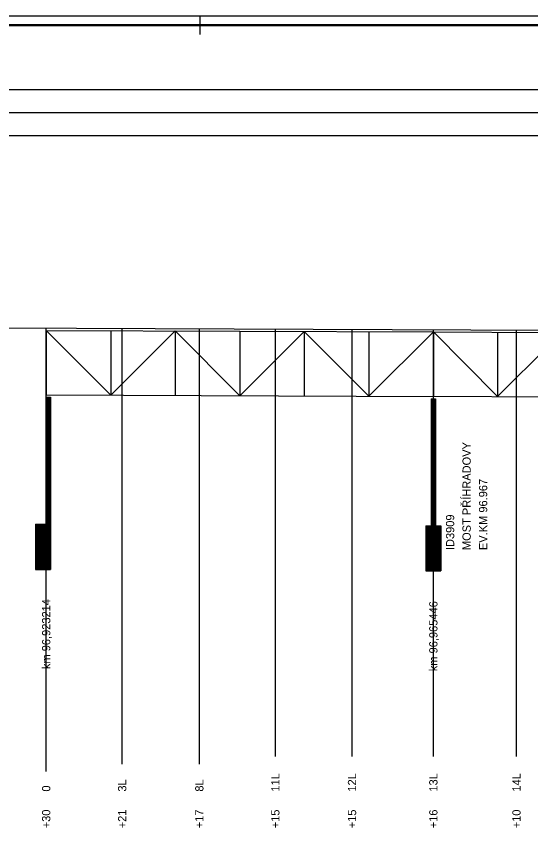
# Model space of a CAD drawing. Extents: x 0 to 10087, y -805 to 297.
# Drawn here: x 1219.9 to 1332.1, y 120.1 to 297 of the extents above; entities that cross this region are included whole.
import ezdxf

# ---------------------------------------------------------------- set-up
doc = ezdxf.new("R2010")
doc.units = 0
for name, color, linetype in [('CARKY_HODNOT', 7, 'Continuous'), ('NIVELETA_CARA', 7, 'Continuous'), ('OBJEKTY_TEXT', 7, 'Continuous'), ('OBJEKTY_TVAR', 7, 'Continuous'), ('RAM', 7, 'Continuous'), ('TEXT', 7, 'Continuous')]:
    doc.layers.add(name, color=color, linetype=linetype)

msp = doc.modelspace()

# ---------------------------------------------------------------- linework, layer by layer
at = {"layer": 'CARKY_HODNOT'}
for p, q in [((1226.43, 138.35), (1226.43, 229.03)), ((1243.01, 138.35), (1243.01, 228.96)), ((1259.84, 138.35), (1259.84, 228.89)), ((1276.42, 138.35), (1276.42, 228.82)), ((1293.15, 138.35), (1293.15, 228.75)), ((1310.89, 138.35), (1310.89, 228.68)), ((1329.03, 138.35), (1329.03, 228.6)), ((1226.43, 132.35), (1226.43, 138.35)), ((1243.01, 134), (1243.01, 138.35)), ((1259.84, 134), (1259.84, 138.35)), ((1276.42, 135.65), (1276.42, 138.35)), ((1293.15, 135.65), (1293.15, 138.35)), ((1310.89, 135.65), (1310.89, 138.35)), ((1329.03, 135.65), (1329.03, 138.35))]:
    msp.add_line(p, q, dxfattribs=at)
at = {"layer": 'NIVELETA_CARA'}
for p, q in [((300, 281), (8321.33, 281)), ((300, 276), (8321.33, 276)), ((300, 271), (8321.33, 271)), ((1153.84, 229.33), (1363.14, 228.46))]:
    msp.add_line(p, q, dxfattribs=at)
at = {"layer": 'OBJEKTY_TVAR'}
for p, q in [((1226.43, 228.53), (1240.5, 214.39)), ((1226.43, 228.53), (1226.43, 214.45)), ((1226.43, 228.53), (1310.89, 228.18)), ((1240.5, 228.47), (1240.5, 214.39)), ((1240.5, 214.39), (1254.58, 228.41)), ((1254.58, 228.41), (1254.58, 214.33)), ((1254.58, 228.41), (1268.66, 214.28)), ((1268.66, 228.35), (1268.66, 214.28)), ((1268.66, 214.28), (1282.74, 228.29)), ((1282.74, 228.29), (1282.74, 214.22)), ((1282.74, 228.29), (1296.81, 214.16)), ((1296.81, 228.24), (1296.81, 214.16)), ((1296.81, 214.16), (1310.89, 228.18)), ((1310.89, 228.18), (1310.89, 214.1)), ((1310.89, 228.18), (1324.9, 214.11)), ((1310.89, 228.18), (1310.89, 214.17)), ((1310.89, 228.18), (1394.92, 227.81)), ((1324.9, 228.12), (1324.9, 214.11)), ((1324.9, 214.11), (1338.9, 228.06)), ((1226.43, 214.45), (1310.89, 214.1)), ((1310.89, 214.17), (1394.92, 213.81)), ((1226.43, 213.95), (1226.43, 186.3)), ((1226.43, 213.95), (1227.37, 213.95)), ((1226.53, 213.95), (1226.53, 186.3)), ((1226.63, 213.95), (1226.63, 186.3)), ((1226.73, 213.95), (1226.73, 186.3)), ((1226.83, 213.95), (1226.83, 186.3)), ((1226.9, 213.95), (1226.9, 186.3)), ((1226.93, 213.95), (1226.93, 186.3)), ((1227.03, 213.95), (1227.03, 186.3)), ((1227.13, 213.95), (1227.13, 186.3)), ((1227.23, 213.95), (1227.23, 186.3)), ((1227.33, 213.95), (1227.33, 186.3)), ((1227.37, 213.95), (1227.37, 186.3)), ((1310.42, 213.6), (1310.42, 185.95)), ((1310.42, 213.6), (1311.36, 213.6)), ((1310.52, 213.6), (1310.52, 185.95)), ((1310.62, 213.6), (1310.62, 185.95)), ((1310.72, 213.6), (1310.72, 185.95)), ((1310.82, 213.6), (1310.82, 185.95)), ((1310.89, 213.6), (1310.89, 185.95)), ((1310.92, 213.6), (1310.92, 185.95)), ((1311.02, 213.6), (1311.02, 185.95)), ((1311.12, 213.6), (1311.12, 185.95)), ((1311.22, 213.6), (1311.22, 185.95)), ((1311.32, 213.6), (1311.32, 185.95)), ((1311.36, 213.6), (1311.36, 185.95)), ((1224.08, 186.3), (1227.37, 186.3)), ((1224.08, 186.3), (1224.08, 176.44)), ((1224.08, 186.2), (1227.37, 186.2)), ((1224.08, 186.1), (1227.37, 186.1)), ((1224.08, 186), (1227.37, 186)), ((1224.08, 185.9), (1227.37, 185.9)), ((1224.08, 185.8), (1227.37, 185.8)), ((1227.37, 186.3), (1227.37, 176.44)), ((1309.25, 185.95), (1312.53, 185.95)), ((1309.25, 185.95), (1309.25, 176.09)), ((1309.25, 185.85), (1312.53, 185.85)), ((1309.25, 185.75), (1312.53, 185.75)), ((1312.53, 185.95), (1312.53, 176.09)), ((1224.08, 185.7), (1227.37, 185.7)), ((1224.08, 185.6), (1227.37, 185.6)), ((1224.08, 185.5), (1227.37, 185.5)), ((1224.08, 185.4), (1227.37, 185.4)), ((1224.08, 185.3), (1227.37, 185.3)), ((1224.08, 185.2), (1227.37, 185.2)), ((1224.08, 185.1), (1227.37, 185.1)), ((1224.08, 185), (1227.37, 185)), ((1224.08, 184.9), (1227.37, 184.9)), ((1224.08, 184.8), (1227.37, 184.8)), ((1224.08, 184.7), (1227.37, 184.7)), ((1224.08, 184.6), (1227.37, 184.6)), ((1224.08, 184.5), (1227.37, 184.5)), ((1224.08, 184.4), (1227.37, 184.4)), ((1224.08, 184.3), (1227.37, 184.3)), ((1224.08, 184.2), (1227.37, 184.2)), ((1224.08, 184.1), (1227.37, 184.1)), ((1224.08, 184), (1227.37, 184)), ((1309.25, 185.65), (1312.53, 185.65)), ((1309.25, 185.55), (1312.53, 185.55)), ((1309.25, 185.45), (1312.53, 185.45)), ((1309.25, 185.35), (1312.53, 185.35)), ((1309.25, 185.25), (1312.53, 185.25)), ((1309.25, 185.15), (1312.53, 185.15)), ((1309.25, 185.05), (1312.53, 185.05)), ((1309.25, 184.95), (1312.53, 184.95)), ((1309.25, 184.85), (1312.53, 184.85)), ((1309.25, 184.75), (1312.53, 184.75)), ((1309.25, 184.65), (1312.53, 184.65)), ((1309.25, 184.55), (1312.53, 184.55)), ((1309.25, 184.45), (1312.53, 184.45)), ((1309.25, 184.35), (1312.53, 184.35)), ((1309.25, 184.25), (1312.53, 184.25)), ((1309.25, 184.15), (1312.53, 184.15)), ((1309.25, 184.05), (1312.53, 184.05)), ((1224.08, 183.9), (1227.37, 183.9)), ((1224.08, 183.8), (1227.37, 183.8)), ((1224.08, 183.7), (1227.37, 183.7)), ((1224.08, 183.6), (1227.37, 183.6)), ((1224.08, 183.5), (1227.37, 183.5)), ((1224.08, 183.4), (1227.37, 183.4)), ((1224.08, 183.3), (1227.37, 183.3)), ((1224.08, 183.2), (1227.37, 183.2)), ((1224.08, 183.1), (1227.37, 183.1)), ((1224.08, 183), (1227.37, 183)), ((1224.08, 182.9), (1227.37, 182.9)), ((1224.08, 182.8), (1227.37, 182.8)), ((1224.08, 182.7), (1227.37, 182.7)), ((1224.08, 182.6), (1227.37, 182.6)), ((1224.08, 182.5), (1227.37, 182.5)), ((1224.08, 182.4), (1227.37, 182.4)), ((1224.08, 182.3), (1227.37, 182.3)), ((1224.08, 182.2), (1227.37, 182.2)), ((1309.25, 183.95), (1312.53, 183.95)), ((1309.25, 183.85), (1312.53, 183.85)), ((1309.25, 183.75), (1312.53, 183.75)), ((1309.25, 183.65), (1312.53, 183.65)), ((1309.25, 183.55), (1312.53, 183.55)), ((1309.25, 183.45), (1312.53, 183.45)), ((1309.25, 183.35), (1312.53, 183.35)), ((1309.25, 183.25), (1312.53, 183.25)), ((1309.25, 183.15), (1312.53, 183.15)), ((1309.25, 183.05), (1312.53, 183.05)), ((1309.25, 182.95), (1312.53, 182.95)), ((1309.25, 182.85), (1312.53, 182.85)), ((1309.25, 182.75), (1312.53, 182.75)), ((1309.25, 182.65), (1312.53, 182.65)), ((1309.25, 182.55), (1312.53, 182.55)), ((1309.25, 182.45), (1312.53, 182.45)), ((1309.25, 182.35), (1312.53, 182.35)), ((1309.25, 182.25), (1312.53, 182.25)), ((1224.08, 182.1), (1227.37, 182.1)), ((1224.08, 182), (1227.37, 182)), ((1224.08, 181.9), (1227.37, 181.9)), ((1224.08, 181.8), (1227.37, 181.8)), ((1224.08, 181.7), (1227.37, 181.7)), ((1224.08, 181.6), (1227.37, 181.6)), ((1224.08, 181.5), (1227.37, 181.5)), ((1224.08, 181.4), (1227.37, 181.4)), ((1224.08, 181.3), (1227.37, 181.3)), ((1224.08, 181.2), (1227.37, 181.2)), ((1224.08, 181.1), (1227.37, 181.1)), ((1224.08, 181), (1227.37, 181)), ((1224.08, 180.9), (1227.37, 180.9)), ((1224.08, 180.8), (1227.37, 180.8)), ((1224.08, 180.7), (1227.37, 180.7)), ((1224.08, 180.6), (1227.37, 180.6)), ((1224.08, 180.5), (1227.37, 180.5)), ((1309.25, 182.15), (1312.53, 182.15)), ((1309.25, 182.05), (1312.53, 182.05)), ((1309.25, 181.95), (1312.53, 181.95)), ((1309.25, 181.85), (1312.53, 181.85)), ((1309.25, 181.75), (1312.53, 181.75)), ((1309.25, 181.65), (1312.53, 181.65)), ((1309.25, 181.55), (1312.53, 181.55)), ((1309.25, 181.45), (1312.53, 181.45)), ((1309.25, 181.35), (1312.53, 181.35)), ((1309.25, 181.25), (1312.53, 181.25)), ((1309.25, 181.15), (1312.53, 181.15)), ((1309.25, 181.05), (1312.53, 181.05)), ((1309.25, 180.95), (1312.53, 180.95)), ((1309.25, 180.85), (1312.53, 180.85)), ((1309.25, 180.75), (1312.53, 180.75)), ((1309.25, 180.65), (1312.53, 180.65)), ((1309.25, 180.55), (1312.53, 180.55)), ((1309.25, 180.45), (1312.53, 180.45)), ((1224.08, 180.4), (1227.37, 180.4)), ((1224.08, 180.3), (1227.37, 180.3)), ((1224.08, 180.2), (1227.37, 180.2)), ((1224.08, 180.1), (1227.37, 180.1)), ((1224.08, 180), (1227.37, 180)), ((1224.08, 179.9), (1227.37, 179.9)), ((1224.08, 179.8), (1227.37, 179.8)), ((1224.08, 179.7), (1227.37, 179.7)), ((1224.08, 179.6), (1227.37, 179.6)), ((1224.08, 179.5), (1227.37, 179.5)), ((1224.08, 179.4), (1227.37, 179.4)), ((1224.08, 179.3), (1227.37, 179.3)), ((1224.08, 179.2), (1227.37, 179.2)), ((1224.08, 179.1), (1227.37, 179.1)), ((1224.08, 179), (1227.37, 179)), ((1224.08, 178.9), (1227.37, 178.9)), ((1224.08, 178.8), (1227.37, 178.8)), ((1224.08, 178.7), (1227.37, 178.7)), ((1309.25, 180.35), (1312.53, 180.35)), ((1309.25, 180.25), (1312.53, 180.25)), ((1309.25, 180.15), (1312.53, 180.15)), ((1309.25, 180.05), (1312.53, 180.05)), ((1309.25, 179.95), (1312.53, 179.95)), ((1309.25, 179.85), (1312.53, 179.85)), ((1309.25, 179.75), (1312.53, 179.75)), ((1309.25, 179.65), (1312.53, 179.65)), ((1309.25, 179.55), (1312.53, 179.55)), ((1309.25, 179.45), (1312.53, 179.45)), ((1309.25, 179.35), (1312.53, 179.35)), ((1309.25, 179.25), (1312.53, 179.25)), ((1309.25, 179.15), (1312.53, 179.15)), ((1309.25, 179.05), (1312.53, 179.05)), ((1309.25, 178.95), (1312.53, 178.95)), ((1309.25, 178.85), (1312.53, 178.85)), ((1309.25, 178.75), (1312.53, 178.75)), ((1224.08, 178.6), (1227.37, 178.6)), ((1224.08, 178.5), (1227.37, 178.5)), ((1224.08, 178.4), (1227.37, 178.4)), ((1224.08, 178.3), (1227.37, 178.3)), ((1224.08, 178.2), (1227.37, 178.2)), ((1224.08, 178.1), (1227.37, 178.1)), ((1224.08, 178), (1227.37, 178)), ((1224.08, 177.9), (1227.37, 177.9)), ((1224.08, 177.8), (1227.37, 177.8)), ((1224.08, 177.7), (1227.37, 177.7)), ((1224.08, 177.6), (1227.37, 177.6)), ((1224.08, 177.5), (1227.37, 177.5)), ((1224.08, 177.4), (1227.37, 177.4)), ((1224.08, 177.3), (1227.37, 177.3)), ((1224.08, 177.2), (1227.37, 177.2)), ((1224.08, 177.1), (1227.37, 177.1)), ((1224.08, 177), (1227.37, 177)), ((1224.08, 176.9), (1227.37, 176.9)), ((1309.25, 178.65), (1312.53, 178.65)), ((1309.25, 178.55), (1312.53, 178.55)), ((1309.25, 178.45), (1312.53, 178.45)), ((1309.25, 178.35), (1312.53, 178.35)), ((1309.25, 178.25), (1312.53, 178.25)), ((1309.25, 178.15), (1312.53, 178.15)), ((1309.25, 178.05), (1312.53, 178.05)), ((1309.25, 177.95), (1312.53, 177.95)), ((1309.25, 177.85), (1312.53, 177.85)), ((1309.25, 177.75), (1312.53, 177.75)), ((1309.25, 177.65), (1312.53, 177.65)), ((1309.25, 177.55), (1312.53, 177.55)), ((1309.25, 177.45), (1312.53, 177.45)), ((1309.25, 177.35), (1312.53, 177.35)), ((1309.25, 177.25), (1312.53, 177.25)), ((1309.25, 177.15), (1312.53, 177.15)), ((1309.25, 177.05), (1312.53, 177.05)), ((1309.25, 176.95), (1312.53, 176.95)), ((1224.08, 176.8), (1227.37, 176.8)), ((1224.08, 176.7), (1227.37, 176.7)), ((1224.08, 176.6), (1227.37, 176.6)), ((1224.08, 176.5), (1227.37, 176.5)), ((1224.08, 176.44), (1227.37, 176.44)), ((1309.25, 176.85), (1312.53, 176.85)), ((1309.25, 176.75), (1312.53, 176.75)), ((1309.25, 176.65), (1312.53, 176.65)), ((1309.25, 176.55), (1312.53, 176.55)), ((1309.25, 176.45), (1312.53, 176.45)), ((1309.25, 176.35), (1312.53, 176.35)), ((1309.25, 176.25), (1312.53, 176.25)), ((1309.25, 176.15), (1312.53, 176.15)), ((1309.25, 176.09), (1312.53, 176.09))]:
    msp.add_line(p, q, dxfattribs=at)
at = {"layer": 'RAM'}
for p, q in [((8636.33, 297), (0, 297)), ((1260, 293), (1260, 297)), ((8634.33, 295.1), (2, 295.1)), ((8634.33, 295), (2, 295)), ((8634.33, 294.9), (2, 294.9))]:
    msp.add_line(p, q, dxfattribs=at)

# ---------------------------------------------------------------- texts
at = {"layer": 'OBJEKTY_TEXT'}
for s, p in [('MOST PŘÍHRADOVY', (1319.05, 180.64)), ('EV.KM 96.967', (1322.65, 180.64)), ('ID3909', (1315.45, 180.64)), ('km 96,923214', (1227.33, 154.7)), ('km 96,965446', (1311.79, 154.24))]:
    msp.add_text(s, height=1.8, rotation=90, dxfattribs=at).set_placement(p)
at = {"layer": 'TEXT'}
for s, p in [('11L', (1277.32, 128)), ('12L', (1294.05, 128)), ('13L', (1311.79, 128)), ('14L', (1329.93, 128)), ('0', (1227.33, 128)), ('3L', (1243.91, 128)), ('8L', (1260.74, 128)), ('+30', (1227.33, 120)), ('+21', (1243.91, 120)), ('+17', (1260.74, 120)), ('+15', (1277.32, 120)), ('+15', (1294.05, 120)), ('+16', (1311.79, 120)), ('+10', (1329.93, 120))]:
    msp.add_text(s, height=1.8, rotation=90, dxfattribs=at).set_placement(p)

doc.saveas('drawing.dxf')
